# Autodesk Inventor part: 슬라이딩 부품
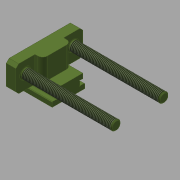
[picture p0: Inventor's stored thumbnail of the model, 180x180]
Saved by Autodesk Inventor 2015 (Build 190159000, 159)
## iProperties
Created: 2017-04
Part Number: 슬라이딩 부품
Material: 강철, 연강
Document SubType Name: Modeling
Designer: mduedu
Density: 7.86 g/cm^3
Appearance: 올리브 녹색
Mass: 395.304 g
Surface Area: 150.948 cm^2
Volume: 50.2931 cm^3
Author: mduedu
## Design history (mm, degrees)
sketch "스케치1"
  geometry: L1 (37, 35)-(10, 35); L2 (0, 17)-(0, 0); L3 (0, 17)-(5, 17); L4 (5, 17)-(5, 12); L5 (5, 12)-(10, 12); L6 (10, 12)-(10, 35); L7 (37, 35)-(37, 0); L8 (37, 0)-(0, 0); L9 (37, -35)-(10, -35); L10 (0, -17)-(0, 0); L11 (0, -17)-(5, -17); L12 (5, -17)-(5, -12); L13 (5, -12)-(10, -12); L14 (10, -12)-(10, -35); L15 (37, -35)-(37, 0)
  constraints: 30 end point, 6 symmetric about line, 3 perpendicular, 2 horizontal, 2 point on line, 2 vertical
  dimensions: "d39" = 5 distance of L2.start L3.end; "d41" = 70 distance between parallel lines of L9 L1; "d42" = 27 distance of L9.start L9.end; "d43" = 24 distance between parallel lines of L13 L5; "d44" = 5 distance of L4.end L5.end; "d45" = 34 distance between parallel lines of L11 L3
extrude "돌출1" new body sketch "스케치1" distance "d5" = 10; taper "d6" = 0 deg
sketch "스케치2"
  geometry: L1 (-35, 10)-(-35, 37) reference; L2 (17, 0)-(-17, 0) reference; L3 (-17, 0)-(-17, 5) reference; L4 (-17, 5)-(-12, 5) reference; L5 (-12, 5)-(-12, 10) reference; L6 (-12, 10)-(-35, 10) reference; L7 (-35, 37)-(35, 37) reference; L8 (35, 37)-(35, 10) reference; L9 (35, 10)-(12, 10) reference; L10 (12, 10)-(12, 5) reference; L11 (12, 5)-(17, 5) reference; L12 (17, 5)-(17, 0) reference; L13 (-12, 10)-(-15, 10); L14 (-15, 10)-(-15, 15); L15 (-15, 15)-(15, 15); L16 (15, 15)-(15, 10); L17 (15, 10)-(12, 10)
  constraints: 10 end point, 4 perpendicular, 2 point on line
  dimensions: "d46" = 3 distance between parallel lines of L14 L5; "d47" = 3 distance between parallel lines of L16 L10 (= d46); "d48" = 5 distance of L13.end L14.end
extrude "돌출2" join sketch "스케치2" distance "d12" = 20; taper "d13" = 0 deg
sketch "스케치3"
  geometry: L1 (0, 20)-(8, 20); L2 (8, 20)-(8, 50); L3 (8, 50)-(0, 50); L4 (0, 50)-(0, 20); L5 (0, 50)-(20, 50) reference; L6 (0, 20)-(20, 20) reference; L7 (0, 0)-(0, 70) reference; 2 further points
  constraints: 8 end point, 2 midpoint, 2 parallel, 1 horizontal, 1 perpendicular, 1 point on line
  dimensions: "d14" = 8 distance between parallel lines of L2 L4
extrude "돌출3" join sketch "스케치3" stored distance "d16" = 20; taper "d17" = 0 deg
fillet "모깎기1" dims "d18" = 5
sketch "스케치4"
  geometry: L1 (-15, 10)-(-35, 10) reference; L2 (-35, 10)-(-35, 37) reference; C1 r 5 at (-25, 25); 1 further point
  constraints: 1 centre point
  dimensions: "d19" = 10 diameter of C1; "d23" = 25 horizontal distance of point (0, 0) C1.centre (derived); "d49" = 15 distance from line of C1.centre L1; "d50" = 10 distance from line of C1.centre L2
extrude "돌출4" join sketch "스케치4" distance "d24" = 95; taper "d25" = 0 deg
feature "스레드1" dims "d26" = 10, "d27" = 0
chamfer "모따기1" distance "d28" = 1; stored, may be unused: second distance "d29" = 2, angle "d30" = 45 deg
fillet "모깎기2" dims "d31" = 1
sketch "스케치5"
  geometry: L1 (-12, 5)-(-12, 10) reference; L2 (12, 10)-(12, 5) reference; C1 r 0.5 at (-12, 10); C2 r 0.5 at (-12, 5); C3 r 0.5 at (12, 5); C4 r 0.5 at (12, 10); 1 further point
  constraints: 4 centre point, 4 coincident, 3 equal radius
  dimensions: "d51" = 1 diameter of C1
extrude "돌출5" cut sketch "스케치5" stored distance "d34" = 89; taper "d35" = 0 deg
chamfer "모따기2" distance "d36" = 3; stored, may be unused: second distance "d37" = 2, angle "d38" = 45 deg
chamfer "모따기3" distance "d52" = 0.5; stored, may be unused: second distance "d53" = 2, angle "d54" = 45 deg
mirror "대칭2"
node "솔리드2"
node "투영된 루프1"
node "솔리드1"
